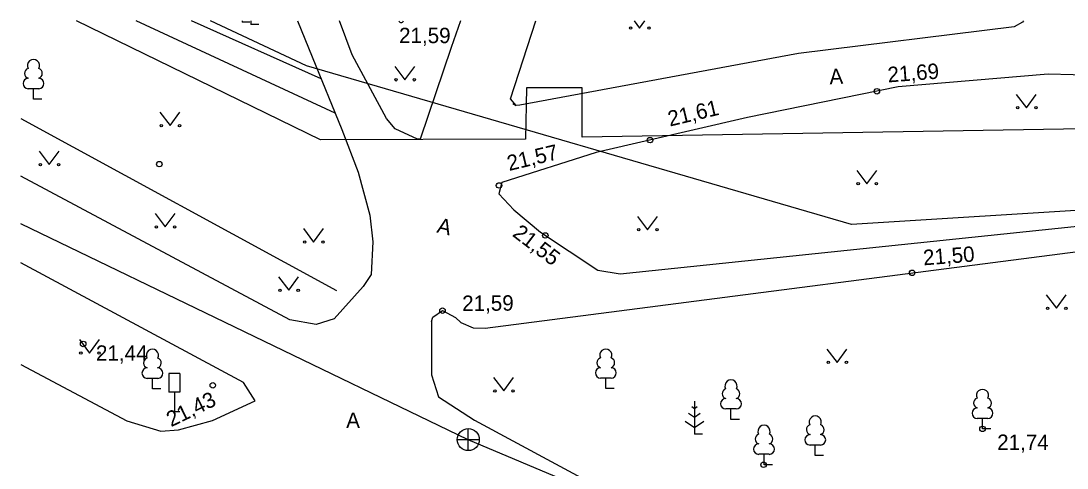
# Model space of a CAD drawing. Extents: x 714038 to 714279, y 6589845 to 6590041.
# Drawn here: x 714037.81 to 714085.35, y 6590020.65 to 6590040.97 of the extents above; entities that cross this region are included whole.
import ezdxf

# ---------------------------------------------------------------- set-up
doc = ezdxf.new("R2010")
doc.units = 0
for name, color, linetype in [('HALJASTUS', 7, 'Continuous'), ('KKAEV', 7, 'Continuous'), ('KORGUS', 7, 'Continuous'), ('KTRASS', 7, 'Continuous'), ('LIIKLUS', 7, 'Continuous'), ('MPKAABEL', 7, 'Continuous'), ('PUU', 7, 'Continuous'), ('TEE', 7, 'Continuous'), ('TTRASS', 7, 'Continuous')]:
    doc.layers.add(name, color=color, linetype=linetype)

msp = doc.modelspace()

# ---------------------------------------------------------------- linework, layer by layer
at = {"layer": 'HALJASTUS'}
for p, q in [((714065.672, 6590040.965), (714065.92, 6590040.64)), ((714065.92, 6590040.64), (714066.159, 6590040.965)), ((714054.797, 6590038.897), (714055.26, 6590038.29)), ((714055.26, 6590038.29), (714055.706, 6590038.897)), ((714083.047, 6590037.627), (714083.51, 6590037.02)), ((714083.51, 6590037.02), (714083.956, 6590037.627)), ((714044.127, 6590036.817), (714044.59, 6590036.21)), ((714044.59, 6590036.21), (714045.036, 6590036.817)), ((714038.633, 6590035.046), (714039.096, 6590034.439)), ((714039.096, 6590034.439), (714039.542, 6590035.046)), ((714075.797, 6590034.177), (714076.26, 6590033.57)), ((714076.26, 6590033.57), (714076.706, 6590034.177)), ((714043.904, 6590032.21), (714044.368, 6590031.603)), ((714044.368, 6590031.603), (714044.813, 6590032.21)), ((714065.827, 6590032.087), (714066.29, 6590031.48)), ((714066.29, 6590031.48), (714066.736, 6590032.087)), ((714050.647, 6590031.527), (714051.11, 6590030.92)), ((714051.11, 6590030.92), (714051.556, 6590031.527)), ((714049.517, 6590029.337), (714049.981, 6590028.73)), ((714049.981, 6590028.73), (714050.426, 6590029.337)), ((714084.407, 6590028.517), (714084.87, 6590027.91)), ((714084.87, 6590027.91), (714085.316, 6590028.517)), ((714040.471, 6590026.484), (714040.934, 6590025.878)), ((714040.934, 6590025.878), (714041.38, 6590026.484)), ((714074.437, 6590026.057), (714074.9, 6590025.45)), ((714074.9, 6590025.45), (714075.346, 6590026.057)), ((714059.287, 6590024.762), (714059.75, 6590024.156)), ((714059.75, 6590024.156), (714060.196, 6590024.762))]:
    msp.add_line(p, q, dxfattribs=at)
msp.add_lwpolyline([(714037.81, 6590036.525), (714052.159, 6590028.713)], dxfattribs=at)
for centre in [(714065.519, 6590040.64), (714066.348, 6590040.64), (714054.859, 6590038.29), (714055.688, 6590038.29), (714083.109, 6590037.02), (714083.938, 6590037.02), (714044.189, 6590036.21), (714045.018, 6590036.21), (714038.695, 6590034.439), (714039.524, 6590034.439), (714075.859, 6590033.57), (714076.688, 6590033.57), (714043.967, 6590031.603), (714044.795, 6590031.603), (714065.889, 6590031.48), (714066.718, 6590031.48), (714050.709, 6590030.92), (714051.538, 6590030.92), (714049.58, 6590028.73), (714050.409, 6590028.73), (714084.469, 6590027.91), (714085.298, 6590027.91), (714040.533, 6590025.878), (714041.362, 6590025.878), (714074.499, 6590025.45), (714075.328, 6590025.45), (714059.349, 6590024.156), (714060.178, 6590024.156)]:
    msp.add_circle(centre, 0.055, dxfattribs=at)
at = {"layer": 'KKAEV'}
for p, q in [((714058.142, 6590021.444), (714058.142, 6590022.444)), ((714057.642, 6590021.944), (714058.642, 6590021.944))]:
    msp.add_line(p, q, dxfattribs=at)
msp.add_circle((714058.142, 6590021.944), 0.5, dxfattribs=at)
at = {"layer": 'KORGUS'}
for centre in [(714076.71, 6590037.77), (714066.4, 6590035.55), (714044.1, 6590034.46), (714059.54, 6590033.49), (714061.64, 6590031.22), (714078.31, 6590029.52), (714056.97, 6590027.8), (714040.64, 6590026.29), (714046.53, 6590024.41), (714081.51, 6590022.43), (714071.56, 6590020.8)]:
    msp.add_circle(centre, 0.125, dxfattribs=at)
msp.add_arc((714055.09, 6590041.02), 0.125, 206.0754, 333.9246, dxfattribs=at)
at = {"layer": 'KTRASS'}
for points in [[(714058.132, 6590021.931), (714037.81, 6590031.753)], [(714108.526, 6590000.746), (714093.581, 6590006.995), (714058.132, 6590021.931)]]:
    msp.add_lwpolyline(points, dxfattribs=at)
at = {"layer": 'LIIKLUS'}
for points in [[(714044.539, 6590024.95), (714044.539, 6590024.1)], [(714045.039, 6590024.95), (714044.539, 6590024.95)], [(714045.039, 6590024.95), (714045.039, 6590024.1)], [(714045.039, 6590024.1), (714044.539, 6590024.1)], [(714044.789, 6590024.1), (714044.789, 6590023.2)], [(714045.039, 6590023.2), (714044.789, 6590023.2)]]:
    msp.add_lwpolyline(points, dxfattribs=at)
at = {"layer": 'MPKAABEL'}
msp.add_lwpolyline([(714096.687, 6590027.681), (714093.35, 6590027.75), (714089.06, 6590029.7), (714087.45, 6590032.46), (714075.56, 6590031.71), (714050.79, 6590038.93), (714046.419, 6590040.965)], dxfattribs=at)
at = {"layer": 'PUU'}
for p, q in [((714047.86, 6590040.965), (714047.86, 6590040.91)), ((714048.22, 6590040.91), (714047.86, 6590040.91)), ((714048.26, 6590040.965), (714048.26, 6590040.8)), ((714048.62, 6590040.8), (714048.26, 6590040.8)), ((714038.62, 6590037.885), (714038.14, 6590037.885)), ((714038.38, 6590037.41), (714038.38, 6590037.885)), ((714038.76, 6590037.41), (714038.38, 6590037.41)), ((714044.025, 6590024.727), (714043.545, 6590024.727)), ((714043.785, 6590024.252), (714043.785, 6590024.727)), ((714064.63, 6590024.735), (714064.15, 6590024.735)), ((714064.39, 6590024.26), (714064.39, 6590024.735)), ((714044.165, 6590024.252), (714043.785, 6590024.252)), ((714064.77, 6590024.26), (714064.39, 6590024.26)), ((714068.419, 6590023.344), (714068.294, 6590023.427)), ((714068.419, 6590023.694), (714068.419, 6590022.194)), ((714068.543, 6590023.427), (714068.419, 6590023.344)), ((714070.32, 6590023.335), (714069.84, 6590023.335)), ((714070.08, 6590022.86), (714070.08, 6590023.335)), ((714068.419, 6590022.944), (714068.152, 6590023.122)), ((714068.685, 6590023.122), (714068.419, 6590022.944)), ((714070.46, 6590022.86), (714070.08, 6590022.86)), ((714081.75, 6590022.905), (714081.27, 6590022.905)), ((714081.51, 6590022.43), (714081.51, 6590022.905)), ((714067.994, 6590022.784), (714068.419, 6590022.501)), ((714068.419, 6590022.501), (714068.843, 6590022.784)), ((714081.89, 6590022.43), (714081.51, 6590022.43)), ((714068.779, 6590022.194), (714068.419, 6590022.194)), ((714074.15, 6590021.695), (714073.67, 6590021.695)), ((714073.91, 6590021.22), (714073.91, 6590021.695)), ((714071.82, 6590021.275), (714071.34, 6590021.275)), ((714071.58, 6590020.8), (714071.58, 6590021.275)), ((714074.29, 6590021.22), (714073.91, 6590021.22)), ((714071.96, 6590020.8), (714071.58, 6590020.8))]:
    msp.add_line(p, q, dxfattribs=at)
for centre, radius, start, end in [((714038.38, 6590038.93), 0.277, 332.5799, 207.4201), ((714038.21, 6590038.583), 0.233, 109.0217, 253.1415), ((714038.55, 6590038.583), 0.233, 286.8508, 70.9859), ((714038.143, 6590038.122), 0.238, 90.0016, 269.3953), ((714038.617, 6590038.122), 0.238, 270.6047, 89.9984), ((714043.785, 6590025.772), 0.277, 332.5799, 207.4201), ((714064.39, 6590025.78), 0.277, 332.5799, 207.4201), ((714043.548, 6590024.964), 0.238, 90.0016, 269.3953), ((714043.615, 6590025.424), 0.233, 109.0217, 253.1415), ((714043.955, 6590025.424), 0.233, 286.8508, 70.9859), ((714044.023, 6590024.964), 0.238, 270.6047, 89.9984), ((714064.153, 6590024.972), 0.238, 90.0016, 269.3953), ((714064.22, 6590025.433), 0.233, 109.0217, 253.1415), ((714064.56, 6590025.433), 0.233, 286.8508, 70.9859), ((714064.627, 6590024.972), 0.238, 270.6047, 89.9984), ((714069.91, 6590024.033), 0.233, 109.0217, 253.1415), ((714070.08, 6590024.38), 0.277, 332.5799, 207.4201), ((714070.25, 6590024.033), 0.233, 286.8508, 70.9859), ((714069.843, 6590023.572), 0.238, 90.0016, 269.3953), ((714070.317, 6590023.572), 0.238, 270.6047, 89.9984), ((714081.34, 6590023.603), 0.233, 109.0217, 253.1415), ((714081.51, 6590023.95), 0.277, 332.5799, 207.4201), ((714081.68, 6590023.603), 0.233, 286.8508, 70.9859), ((714081.273, 6590023.142), 0.238, 90.0016, 269.3953), ((714081.747, 6590023.142), 0.238, 270.6047, 89.9984), ((714073.91, 6590022.74), 0.277, 332.5799, 207.4201), ((714071.58, 6590022.32), 0.277, 332.5799, 207.4201), ((714073.74, 6590022.393), 0.233, 109.0217, 253.1415), ((714074.08, 6590022.393), 0.233, 286.8508, 70.9859), ((714071.41, 6590021.973), 0.233, 109.0217, 253.1415), ((714071.75, 6590021.973), 0.233, 286.8508, 70.9859), ((714073.673, 6590021.932), 0.238, 90.0016, 269.3953), ((714074.147, 6590021.932), 0.238, 270.6047, 89.9984), ((714071.343, 6590021.512), 0.238, 90.0016, 269.3953), ((714071.817, 6590021.512), 0.238, 270.6047, 89.9984)]:
    msp.add_arc(centre, radius, start, end, dxfattribs=at)
at = {"layer": 'TEE'}
for points in [[(714050.378, 6590040.965), (714051.05, 6590039.33), (714052.39, 6590036.03), (714053.13, 6590034.09), (714053.67, 6590032.14), (714053.8, 6590030.93), (714053.73, 6590029.45), (714053.362, 6590028.903), (714052.05, 6590027.43), (714051.232, 6590027.176), (714050.024, 6590027.391), (714037.81, 6590033.905)], [(714052.09, 6590036.78), (714043.054, 6590040.965)], [(714051.45, 6590038.34), (714045.556, 6590040.965)], [(714057.784, 6590040.965), (714057.37, 6590039.76), (714055.96, 6590035.59), (714055.83, 6590035.59), (714054.82, 6590036.06), (714054.42, 6590036.53), (714052.87, 6590039.42), (714052.284, 6590040.965)], [(714083.379, 6590040.965), (714083.334, 6590040.906), (714082.95, 6590040.693), (714073.155, 6590039.49), (714060.491, 6590037.133), (714060.32, 6590037.125), (714060.06, 6590037.433), (714061.21, 6590040.965)], [(714061.418, 6590031.365), (714064.028, 6590029.649), (714065.041, 6590029.48), (714088.138, 6590031.885), (714089.66, 6590032.196), (714090.532, 6590032.585), (714091.13, 6590033.07), (714091.054, 6590033.578), (714088.562, 6590036.861), (714087.579, 6590037.76), (714086.716, 6590038.263), (714086.251, 6590038.431), (714085.627, 6590038.511), (714084.494, 6590038.541), (714077.674, 6590037.967), (714070.836, 6590036.585), (714063.955, 6590034.984), (714059.67, 6590033.631), (714059.535, 6590033.112), (714060.214, 6590032.388), (714061.418, 6590031.365)], [(714060.168, 6590037.217), (714060.32, 6590037.125)], [(714056.537, 6590027.513), (714056.966, 6590027.804), (714057.559, 6590027.491), (714057.807, 6590027.264), (714058.362, 6590027.017), (714058.907, 6590027.007), (714089.829, 6590031.012), (714090.473, 6590031.023), (714090.766, 6590030.875), (714091.01, 6590030.635), (714091.159, 6590030.105), (714091.125, 6590029.656), (714091.141, 6590029.299), (714091.34, 6590028.86), (714091.618, 6590028.64), (714092.164, 6590028.45), (714092.663, 6590028.49), (714093.12, 6590028.689), (714093.575, 6590028.907), (714093.878, 6590028.938), (714094.262, 6590028.758), (714094.522, 6590028.514), (714098.608, 6590023.642)], [(714037.81, 6590025.359), (714042.623, 6590022.79), (714044.166, 6590022.333), (714044.978, 6590022.381), (714046.516, 6590022.819), (714048.449, 6590023.712), (714047.921, 6590024.54), (714037.81, 6590029.974)], [(714056.466, 6590027.31), (714056.537, 6590027.513)], [(714056.466, 6590027.31), (714056.476, 6590024.886), (714056.788, 6590023.888), (714058.417, 6590022.828), (714080.514, 6590010.928), (714103.015, 6589998.807), (714111.415, 6589994.157), (714112.824, 6589994.218)], [(714057.559, 6590027.491), (714057.807, 6590027.264)]]:
    msp.add_lwpolyline(points, dxfattribs=at)
at = {"layer": 'TTRASS'}
msp.add_lwpolyline([(714092.848, 6590036.148), (714086.1, 6590036.06), (714063.31, 6590035.69), (714063.31, 6590037.93), (714060.79, 6590037.93), (714060.74, 6590035.6), (714051.43, 6590035.57), (714040.343, 6590040.965)], dxfattribs=at)

# ---------------------------------------------------------------- texts
at = {"layer": 'KORGUS'}
for s, p in [('21,59', (714054.994, 6590039.955)), ('21,44', (714041.221, 6590025.525)), ('21,74', (714082.176, 6590021.475))]:
    msp.add_text(s, height=0.7, dxfattribs=at).set_placement(p)
for s, rotation, p in [('21,69', 4.3308, (714077.221, 6590038.17)), ('21,61', 13.4237, (714067.303, 6590036.164)), ('21,57', 13.4237, (714059.996, 6590034.146)), ('21,55', 322.8373, (714060.105, 6590031.218)), ('21,50', 4.3308, (714078.836, 6590029.859)), ('21,59', 0.3556, (714057.864, 6590027.787)), ('21,43', 25.9475, (714044.637, 6590022.503))]:
    msp.add_text(s, height=0.7, rotation=rotation, dxfattribs=at).set_placement(p)
at = {"layer": 'TEE'}
for rotation, p in [(2.6756, (714074.566, 6590038.081)), (346.551, (714056.678, 6590031.36))]:
    msp.add_text('A', height=0.7, rotation=rotation, dxfattribs=at).set_placement(p)
msp.add_text('A', height=0.7, dxfattribs=at).set_placement((714052.592, 6590022.474))

doc.saveas('drawing.dxf')
